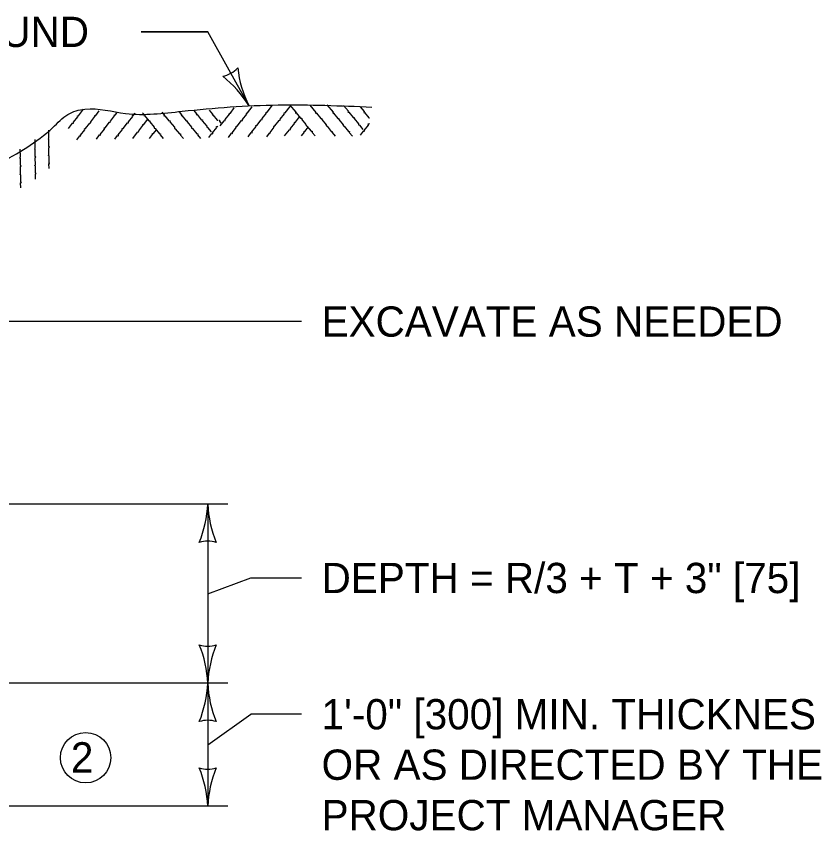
# Model space of a CAD drawing. Extents: x 49991.4 to 50021, y 49987.6 to 50011.4.
# Drawn here: x 50010.762 to 50012.329, y 49992.86 to 49994.474 of the extents above; entities that cross this region are included whole.
import ezdxf

# ---------------------------------------------------------------- set-up
doc = ezdxf.new("R2010")
doc.units = 0
for name, color, linetype in [('Level 1', 7, 'Continuous'), ('Level 2', 7, 'Continuous'), ('Level 3', 7, 'Continuous')]:
    doc.layers.add(name, color=color, linetype=linetype)

msp = doc.modelspace()

# ---------------------------------------------------------------- linework, layer by layer
at = {"layer": 'Level 1'}
for points in [[(50010.8655, 49994.2522), (50010.8733, 49994.2624), (50010.8753, 49994.2629), (50010.8754, 49994.2649), (50010.8837, 49994.2754), (50010.8834, 49994.2774), (50010.8855, 49994.2775), (50010.8952, 49994.2905)], [(50011.144, 49994.2886), (50011.1508, 49994.2806), (50011.15, 49994.279), (50011.1517, 49994.279), (50011.1601, 49994.2685), (50011.1613, 49994.2686)], [(50011.1664, 49994.2571), (50011.1742, 49994.2673), (50011.1761, 49994.2678), (50011.1763, 49994.2698), (50011.1846, 49994.2803), (50011.1843, 49994.2823), (50011.1864, 49994.2824), (50011.1941, 49994.2928)], [(50011.1827, 49994.2344), (50011.1889, 49994.2427), (50011.1906, 49994.2423), (50011.1902, 49994.2438), (50011.1985, 49994.2545), (50011.198, 49994.2566), (50011.2, 49994.2568), (50011.2083, 49994.2677), (50011.2103, 49994.2682), (50011.2105, 49994.2702), (50011.2188, 49994.2807), (50011.2185, 49994.2827), (50011.2205, 49994.2828), (50011.2297, 49994.2951)], [(50011.2216, 49994.2358), (50011.2278, 49994.2441), (50011.2295, 49994.2437), (50011.2291, 49994.2453), (50011.2374, 49994.2559), (50011.2369, 49994.258), (50011.2389, 49994.2582), (50011.2473, 49994.2692), (50011.2492, 49994.2697), (50011.2494, 49994.2716), (50011.2577, 49994.2822), (50011.2574, 49994.2842), (50011.2594, 49994.2843), (50011.2698, 49994.2981)], [(50011.2584, 49994.2357), (50011.2637, 49994.243), (50011.2654, 49994.2426), (50011.265, 49994.2441), (50011.2733, 49994.2548), (50011.2728, 49994.2568), (50011.2748, 49994.2571), (50011.2832, 49994.268), (50011.2851, 49994.2685), (50011.2853, 49994.2705), (50011.2936, 49994.281), (50011.2933, 49994.283), (50011.2953, 49994.2831), (50011.3048, 49994.2957)], [(50011.3035, 49994.2992), (50011.3162, 49994.2844), (50011.3155, 49994.2827), (50011.3171, 49994.2828), (50011.3256, 49994.2723), (50011.3277, 49994.2723), (50011.3275, 49994.2703), (50011.3362, 49994.2597), (50011.3363, 49994.2577), (50011.3382, 49994.257), (50011.3465, 49994.2466), (50011.3486, 49994.2465), (50011.3482, 49994.2444), (50011.3542, 49994.2373)], [(50011.3438, 49994.2984), (50011.3561, 49994.2839), (50011.3554, 49994.2823), (50011.357, 49994.2824), (50011.3655, 49994.2719), (50011.3676, 49994.2719), (50011.3674, 49994.2699), (50011.3762, 49994.2593), (50011.3762, 49994.2573), (50011.3781, 49994.2566), (50011.3864, 49994.2462), (50011.3884, 49994.246), (50011.3881, 49994.244), (50011.3941, 49994.2369)], [(50011.3775, 49994.299), (50011.3902, 49994.2842), (50011.3894, 49994.2826), (50011.391, 49994.2826), (50011.3995, 49994.2722), (50011.4017, 49994.2722), (50011.4014, 49994.2702), (50011.4102, 49994.2596), (50011.4102, 49994.2575), (50011.4121, 49994.2569), (50011.4205, 49994.2464), (50011.4225, 49994.2463), (50011.4221, 49994.2443), (50011.4282, 49994.2372)], [(50011.4103, 49994.2978), (50011.4203, 49994.2862), (50011.4195, 49994.2846), (50011.4211, 49994.2846), (50011.4296, 49994.2741), (50011.4317, 49994.2742), (50011.4315, 49994.2721), (50011.4403, 49994.2616), (50011.4403, 49994.2595), (50011.4422, 49994.2589), (50011.4491, 49994.2502)], [(50011.4435, 49994.2951), (50011.4517, 49994.2855), (50011.4509, 49994.2839), (50011.4525, 49994.2839), (50011.461, 49994.2734), (50011.4621, 49994.2735)], [(50010.8819, 49994.2295), (50010.888, 49994.2378), (50010.8897, 49994.2374), (50010.8893, 49994.2389), (50010.8976, 49994.2496), (50010.8971, 49994.2517), (50010.8991, 49994.2519), (50010.9075, 49994.2628), (50010.9094, 49994.2633), (50010.9096, 49994.2653), (50010.9179, 49994.2758), (50010.9176, 49994.2778), (50010.9196, 49994.2779), (50010.9263, 49994.2868)], [(50010.9208, 49994.2309), (50010.9269, 49994.2392), (50010.9286, 49994.2388), (50010.9282, 49994.2404), (50010.9365, 49994.251), (50010.936, 49994.2531), (50010.938, 49994.2533), (50010.9464, 49994.2643), (50010.9483, 49994.2648), (50010.9485, 49994.2667), (50010.9568, 49994.2773), (50010.9565, 49994.2793), (50010.9586, 49994.2794), (50010.9611, 49994.2828)], [(50010.9575, 49994.2308), (50010.9628, 49994.2381), (50010.9645, 49994.2377), (50010.9641, 49994.2392), (50010.9724, 49994.2499), (50010.9719, 49994.252), (50010.9739, 49994.2522), (50010.9823, 49994.2631), (50010.9842, 49994.2636), (50010.9844, 49994.2656), (50010.9927, 49994.2761), (50010.9924, 49994.2781), (50010.9945, 49994.2782), (50010.9976, 49994.2824)], [(50011.0124, 49994.2829), (50011.0153, 49994.2795), (50011.0146, 49994.2778), (50011.0162, 49994.2779), (50011.0247, 49994.2674), (50011.0268, 49994.2674), (50011.0266, 49994.2654), (50011.0354, 49994.2548), (50011.0354, 49994.2528), (50011.0373, 49994.2521), (50011.0456, 49994.2417), (50011.0477, 49994.2416), (50011.0473, 49994.2395), (50011.0533, 49994.2324)], [(50011.0504, 49994.2847), (50011.0553, 49994.279), (50011.0545, 49994.2774), (50011.0561, 49994.2775), (50011.0646, 49994.267), (50011.0667, 49994.267), (50011.0665, 49994.265), (50011.0753, 49994.2544), (50011.0753, 49994.2524), (50011.0772, 49994.2517), (50011.0855, 49994.2413), (50011.0876, 49994.2412), (50011.0872, 49994.2391), (50011.0932, 49994.232)], [(50011.0846, 49994.2848), (50011.0893, 49994.2793), (50011.0885, 49994.2777), (50011.0901, 49994.2777), (50011.0986, 49994.2673), (50011.1008, 49994.2673), (50011.1005, 49994.2653), (50011.1093, 49994.2547), (50011.1093, 49994.2526), (50011.1112, 49994.252), (50011.1196, 49994.2415), (50011.1216, 49994.2414), (50011.1213, 49994.2394), (50011.1273, 49994.2323)], [(50011.1141, 49994.2875), (50011.1194, 49994.2813), (50011.1186, 49994.2797), (50011.1202, 49994.2797), (50011.1287, 49994.2692), (50011.1309, 49994.2693), (50011.1306, 49994.2672), (50011.1394, 49994.2567), (50011.1394, 49994.2546), (50011.1413, 49994.254), (50011.1482, 49994.2453)], [(50011.2939, 49994.2373), (50011.3034, 49994.2497), (50011.3053, 49994.2502), (50011.3055, 49994.2521), (50011.3139, 49994.2627), (50011.3135, 49994.2646), (50011.3156, 49994.2647), (50011.3234, 49994.2752)], [(50010.993, 49994.2324), (50011.0025, 49994.2448), (50011.0044, 49994.2453), (50011.0047, 49994.2472), (50011.013, 49994.2578), (50011.0126, 49994.2598), (50011.0147, 49994.2598), (50011.0221, 49994.2698)], [(50011.1436, 49994.234), (50011.1496, 49994.2422), (50011.1514, 49994.2418), (50011.151, 49994.2433), (50011.1593, 49994.254), (50011.1587, 49994.2561), (50011.1608, 49994.2563), (50011.1613, 49994.257)], [(50011.1636, 49994.2686), (50011.1647, 49994.2686), (50011.1645, 49994.2666), (50011.1677, 49994.2626)], [(50011.4445, 49994.2389), (50011.4505, 49994.2471), (50011.4523, 49994.2467), (50011.4519, 49994.2482), (50011.4602, 49994.2589), (50011.4596, 49994.261), (50011.4617, 49994.2612), (50011.4622, 49994.2619)], [(50010.8271, 49994.173), (50010.8267, 49994.182), (50010.8283, 49994.1827), (50010.827, 49994.1836), (50010.8269, 49994.1972), (50010.8252, 49994.1984), (50010.8266, 49994.1999), (50010.8264, 49994.2137), (50010.8276, 49994.2152), (50010.8265, 49994.2169), (50010.8265, 49994.2303), (50010.825, 49994.2317), (50010.8265, 49994.233), (50010.8261, 49994.2488)], [(50011.0263, 49994.2324), (50011.0322, 49994.2399), (50011.0319, 49994.2419), (50011.0339, 49994.242), (50011.0396, 49994.2496)], [(50011.3272, 49994.2373), (50011.3331, 49994.2448), (50011.3327, 49994.2468), (50011.3348, 49994.2469), (50011.3405, 49994.2545)], [(50010.8001, 49994.1518), (50010.7998, 49994.1621), (50010.8014, 49994.1629), (50010.8001, 49994.1639), (50010.8, 49994.1773), (50010.7983, 49994.1787), (50010.7998, 49994.1801), (50010.7995, 49994.1939), (50010.8007, 49994.1955), (50010.7996, 49994.1971), (50010.7996, 49994.2106), (50010.7981, 49994.2119), (50010.7996, 49994.2133), (50010.7992, 49994.2305)], [(50010.7707, 49994.1342), (50010.7704, 49994.1445), (50010.772, 49994.1453), (50010.7707, 49994.1462), (50010.7706, 49994.1597), (50010.7689, 49994.1611), (50010.7703, 49994.1625), (50010.77, 49994.1762), (50010.7713, 49994.1778), (50010.7702, 49994.1795), (50010.7702, 49994.1929), (50010.7687, 49994.1943), (50010.7702, 49994.1956), (50010.7698, 49994.2109)]]:
    msp.add_lwpolyline(points, dxfattribs=at)
msp.add_spline([(50010.7266, 49994.1821), (50010.8342, 49994.2539), (50010.8642, 49994.2798), (50010.8981, 49994.2904), (50010.9785, 49994.2819), (50011.0906, 49994.2862), (50011.2809, 49994.2988), (50011.467, 49994.2946)], degree=3, dxfattribs=at)
at = {"layer": 'Level 2'}
msp.add_circle((50010.8993, 49993.0051), 0.05, dxfattribs=at)
at = {"layer": 'Level 3'}
for p, q in [((50011.0097, 49994.4436), (50011.1419, 49994.4436)), ((50011.1419, 49994.4436), (50011.0097, 49994.4436)), ((50011.223, 49994.2974), (50011.1419, 49994.4436)), ((50011.1815, 49993.5078), (50010.3047, 49993.5078)), ((50011.1415, 49993.5078), (50011.1415, 49993.1527)), ((50011.1415, 49993.3302), (50011.2272, 49993.3613)), ((50011.2272, 49993.3613), (50011.3272, 49993.3613)), ((50011.1815, 49993.1527), (50010.3047, 49993.1527)), ((50011.1415, 49993.1527), (50011.1415, 49992.909)), ((50011.1415, 49993.0308), (50011.2272, 49993.0913)), ((50011.3272, 49993.0913), (50011.2272, 49993.0913)), ((50011.1815, 49992.909), (50010.2956, 49992.909))]:
    msp.add_line(p, q, dxfattribs=at)
msp.add_lwpolyline([(50011.3272, 49993.8695), (50010.6045, 49993.8695), (50010.4806, 49994.0016)], dxfattribs=at)
for centre, radius, start, end in [((50011.1608, 49994.4095), 0.0548, 281.1568, 316.8792), ((50011.4217, 49994.3971), 0.2223, 186.474, 206.6575), ((50011.0251, 49994.1744), 0.233, 31.8453, 51.0952), ((50010.9088, 49993.5193), 0.233, 337.9228, 357.1727), ((50011.3636, 49993.5169), 0.2223, 182.3605, 202.544), ((50011.1415, 49993.3796), 0.0548, 72.1388, 107.8612), ((50010.9194, 49993.1435), 0.2223, 2.3605, 22.544), ((50011.1415, 49993.2809), 0.0548, 252.1388, 287.8612), ((50011.3742, 49993.1412), 0.233, 157.9228, 177.1727), ((50010.9088, 49993.1642), 0.233, 337.9228, 357.1727), ((50011.3636, 49993.1618), 0.2223, 182.3605, 202.544), ((50011.1415, 49993.0244), 0.0548, 72.1388, 107.8612), ((50011.1415, 49993.0372), 0.0548, 252.1388, 287.8612), ((50010.9088, 49992.8975), 0.233, 2.8273, 22.0772), ((50011.3636, 49992.8998), 0.2223, 157.456, 177.6395)]:
    msp.add_arc(centre, radius, start, end, dxfattribs=at)

# ---------------------------------------------------------------- texts
at = {"layer": 'Level 2'}
for s, p in [('EXISTING GROUND', (50010.1527, 49994.4136)), ('DEPTH = R/3 + T + 3" [75]', (50011.3672, 49993.3313)), ('1\'-0" [300] MIN. THICKNESS,', (50011.3672, 49993.0613)), ('OR AS DIRECTED BY THE', (50011.3672, 49992.9613)), ('PROJECT MANAGER', (50011.3672, 49992.8613))]:
    msp.add_text(s, height=0.06, dxfattribs=at).set_placement(p)
for s, p in [('EXCAVATE AS NEEDED', (50011.3672, 49993.8395)), ('2', (50010.8701, 49992.9758))]:
    msp.add_text(s, height=0.06, rotation=360, dxfattribs=at).set_placement(p)

doc.saveas('drawing.dxf')
